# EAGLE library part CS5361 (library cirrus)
AUDIO A/D CONVERTOR Stereo 114 dB, 192 kHz, Multi-Bit Audio A/D Converter
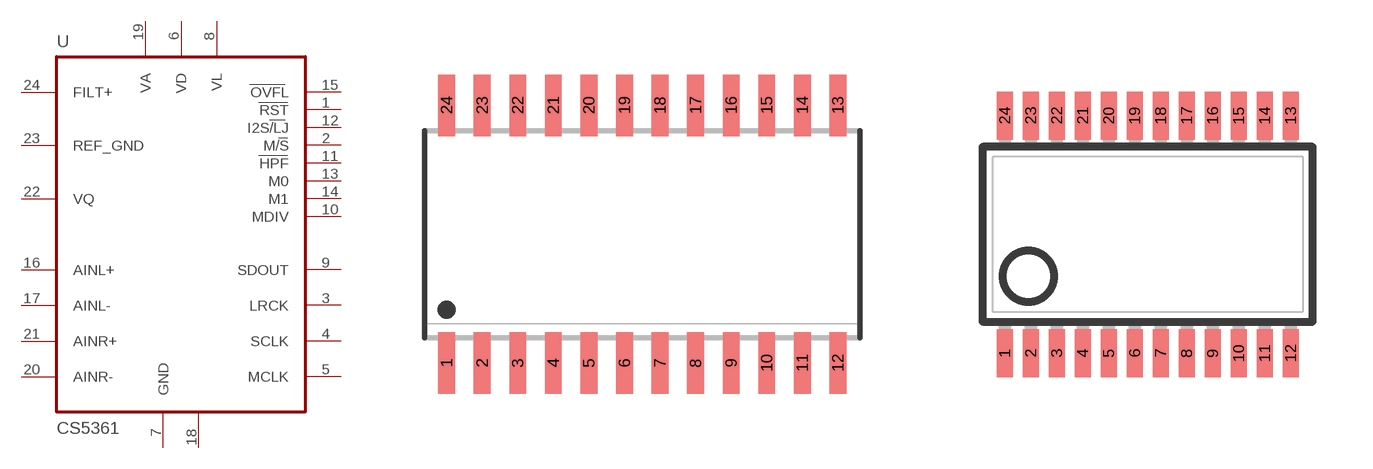
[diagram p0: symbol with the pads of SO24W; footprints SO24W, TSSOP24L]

Designator prefix U

## CS5361-KSZ  [SO24W]
1  RST  in
2  M/S  in
3  LRCK
4  SCLK
5  MCLK  in
6  VD  pwr
7  GND  pwr
8  VL  pwr
9  SDOUT  out
10  MDIV  in
11  HPF  in
12  I2S/LJ  in
13  M0  in
14  M1  in
15  OVFL  out
16  AINL+  pas
17  AINL-  pas
18  GND  pwr
19  VA  pwr
20  AINR-  pas
21  AINR+  pas
22  VQ  pas
23  REF_GND  pas
24  FILT+  pas

## CS5361-KZZ  [TSSOP24L]
Pads as for SO24W

## Footprint SO24W (pad centres in mm)
SMALL OUTLINE INTEGRATED CIRCUIT wide body 7.5 mm/JEDEC MO-119AA
smd 0.6 x 2.2: 1 -6.985,-4.6; 2 -5.715,-4.6; 3 -4.445,-4.6; 4 -3.175,-4.6; 5 -1.905,-4.6; 6 -0.635,-4.6; 7 0.635,-4.6; 8 1.905,-4.6; 9 3.175,-4.6; 10 4.445,-4.6; 11 5.715,-4.6; 12 6.985,-4.6; 13 6.985,4.6; 14 5.715,4.6; 15 4.445,4.6; 16 3.175,4.6; 17 1.905,4.6; 18 0.635,4.6; 19 -0.635,4.6; 20 -1.905,4.6; 21 -3.175,4.6; 22 -4.445,4.6; 23 -5.715,4.6; 24 -6.985,4.6

## Footprint TSSOP24L (pad centres in mm)
Small Shrink Outline Package JEDEC MO-153
smd 0.4 x 1.2: 1 -3.575,-2.97; 2 -2.925,-2.97; 3 -2.275,-2.97; 4 -1.625,-2.97; 5 -0.975,-2.97; 6 -0.325,-2.97; 7 0.325,-2.97; 8 0.975,-2.97; 9 1.625,-2.97; 10 2.275,-2.97; 11 2.925,-2.97; 12 3.575,-2.97; 13 3.575,2.97; 14 2.925,2.97; 15 2.275,2.97; 16 1.625,2.97; 17 0.975,2.97; 18 0.325,2.97; 19 -0.325,2.97; 20 -0.975,2.97; 21 -1.625,2.97; 22 -2.275,2.97; 23 -2.925,2.97; 24 -3.575,2.97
